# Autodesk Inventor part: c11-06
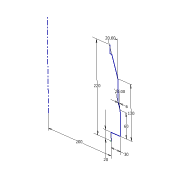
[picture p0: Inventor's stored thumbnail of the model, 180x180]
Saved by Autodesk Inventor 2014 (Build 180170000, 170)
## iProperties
Created: 2011-01
Part Number: c11-06
Material: Aluminum 6061
Document SubType Name: Sheet Metal
Designer: Thom Tremblay
Density: 2.71 g/cm^3
Sheet Metal Rule: Aluminum - 3.4mm
Appearance: Aluminum - Flat
Author: Thom Tremblay
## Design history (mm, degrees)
sketch "Sketch1"
  geometry: L1 (0, 0)-(20, 0); L2 (20, 0)-(20, 30); L3 (20, 30)-(80, 30); L4 (96.485, 24)-(150, 24); L5 (150, 24)-(200, 5.801); L6 (200, 5.801)-(200, 0); L7 (200, 0)-(220, 0); L8 (80, 30)-(96.485, 24); L9 (0, -200)-(220, -200); 1 further point
  constraints: 18 end point, 4 parallel, 3 collinear, 1 coincident, 1 horizontal, 1 perpendicular
  dimensions: "d5" = 20 distance of L1.start L1.end; "d6" = 30 distance of L1.end L2.end; "d7" = 60 distance of L2.end L3.end; "d9" = 220 distance of L7.end point (0, 0); "d11" = 20 deg angle of L5 L4; "d13" = 6 vertical distance of L3.end L4.start; "d14" = 130 distance from line of L4.end L2; "d15" = 20 deg angle of L8 L3; "d16" = 200 distance between parallel lines of L1 L9
body "Solid1"
other parameters: "Thickness" = 3.4 (derived), "BendRadius" = 2 (derived), "BendReliefWidth" = 3.4 (= Thickness), "BendReliefDepth" = 1.7 (= 0.5 x Thickness), "CornerReliefSize" = 13.6 (= 4 x Thickness), "SeamGap" = 0.01, "MinimumRemnant" = 6.8 (= 2 x Thickness), "TransitionRadius" = 2 (= BendRadius), "JacobiRadiusSize" = 2 (= BendRadius), "GapSize" = 3.4 (= Thickness), "d4" = 2 (= BendRadius)
